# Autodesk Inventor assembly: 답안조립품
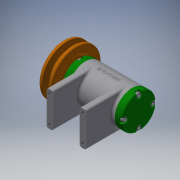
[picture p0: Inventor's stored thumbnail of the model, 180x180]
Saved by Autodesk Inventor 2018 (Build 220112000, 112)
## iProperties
Created: 2020-07
Part Number: 답안조립품
Document SubType Name: Assembly
Designer: Administrator
Author: Administrator
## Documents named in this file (15)
- C:\Users\Administrator\Desktop\700706V1040\답안조립품.iam
- C:\Users\Administrator\Desktop\700706V1040\본체.ipt
- C:\Users\Administrator\Desktop\700706V1040\Ű 3x3x12.ipt
- C:\Users\Administrator\Desktop\700706V1040\V벨트풀리.ipt
- C:\Users\Administrator\Desktop\700706V1040\스프링와셔 8.ipt
- C:\Users\Administrator\Desktop\700706V1040\와셔 6x11.5.ipt
- C:\Users\Administrator\Desktop\700706V1040\축.ipt
- C:\Users\Administrator\Desktop\700706V1040\너트 M8.ipt
- C:\Users\Administrator\Desktop\700706V1040\베어링 6002.ipt
- C:\Users\Administrator\Desktop\700706V1040\뒤커버.ipt
- C:\Users\Administrator\Desktop\700706V1040\앞커버.ipt
- C:\Users\Administrator\Desktop\700706V1040\오일 실 15 25 7.ipt
- C:\Users\Administrator\Desktop\700706V1040\볼트 M4x12.ipt
- C:\Users\Administrator\Desktop\700706V1040\와셔 8x17.ipt
- C:\Users\Administrator\Desktop\700706V1040\볼트 M6x8.ipt
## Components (2 placed, 2 different names)
1. Ű 3x3x12:1 — Insert:9, Mate:3, Mate:4
2. V벨트풀리:1 — Insert:10, Mate:4, Insert:11
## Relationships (5: Insert 3, Mate 2)
- Insert:9: Ű 3x3x12:1
- Mate:3: Ű 3x3x12:1
- Insert:10: V벨트풀리:1
- Mate:4: Ű 3x3x12:1 ↔ V벨트풀리:1
- Insert:11: V벨트풀리:1
